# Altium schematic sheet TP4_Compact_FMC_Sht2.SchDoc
size B; SheetNumber: 2; SheetTotal: 2
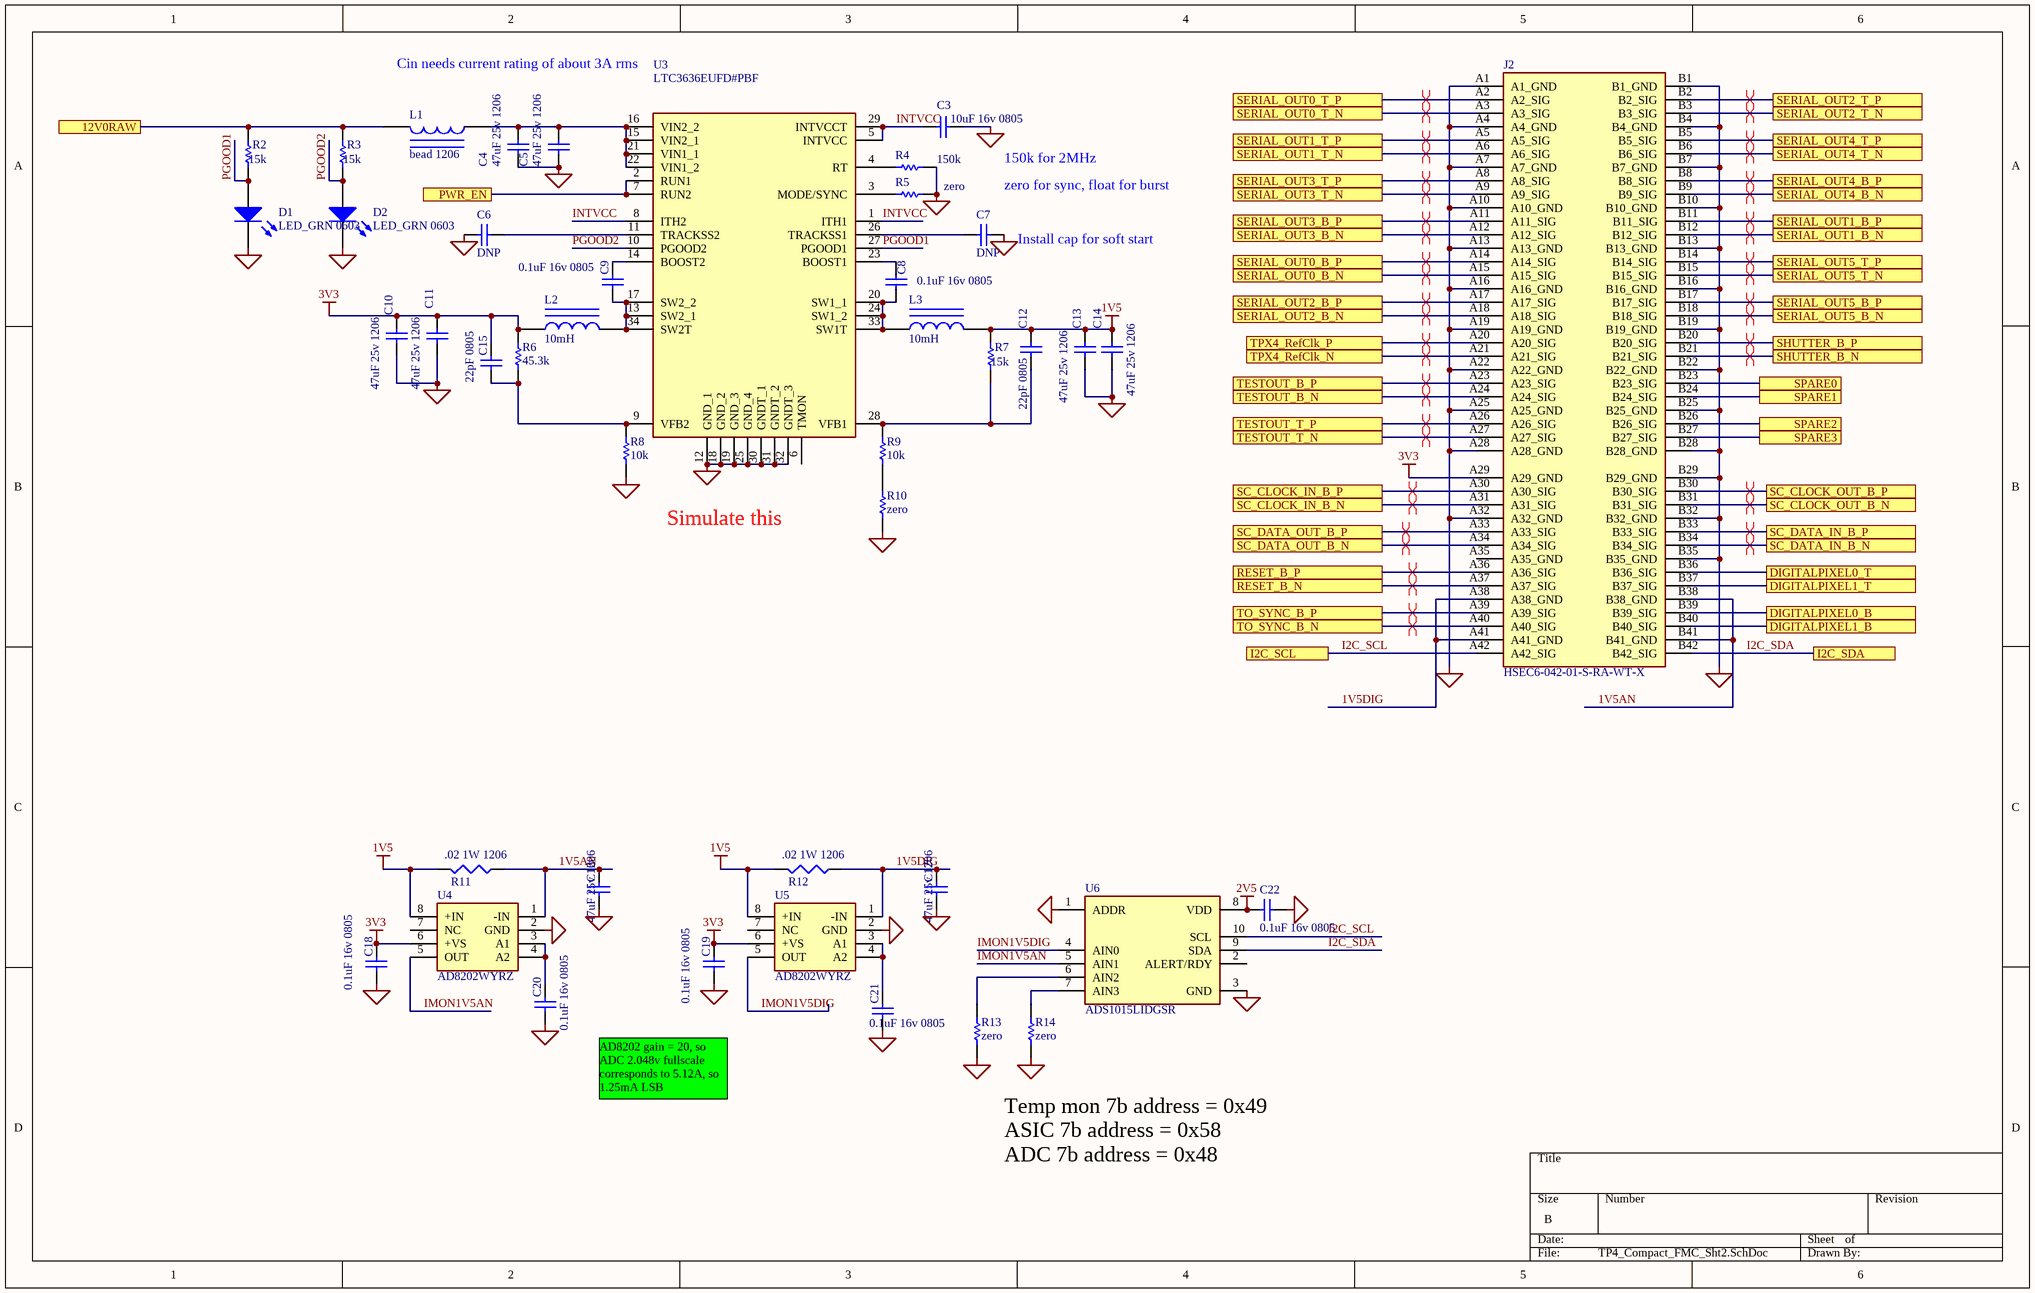
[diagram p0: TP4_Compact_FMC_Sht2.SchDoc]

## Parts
C3  value 10uF 16v 0805  [CAP0805]  (hidden comment: Cap)
C4  value 47uF 25v 1206  [1206]  (hidden comment: Cap)
C5  value 47uF 25v 1206  [1206]  (hidden comment: Cap)
C6  value DNP  [CAP0805]  (hidden comment: Cap)
C7  value DNP  [CAP0805]  (hidden comment: Cap)
C8  value 0.1uF 16v 0805  [CAP0805]  (hidden comment: Cap)
C9  value 0.1uF 16v 0805  [CAP0805]  (hidden comment: Cap)
C10  value 47uF 25v 1206  [1206]  (hidden comment: Cap)
C11  value 47uF 25v 1206  [1206]  (hidden comment: Cap)
C12  value 22pF 0805  [CAP0805]  (hidden comment: Cap)
C13  value 47uF 25v 1206  [1206]  (hidden comment: Cap)
C14  value 47uF 25v 1206  [1206]  (hidden comment: Cap)
C15  value 22pF 0805  [CAP0805]  (hidden comment: Cap)
C16  value 47uF 25v 1206  [1206]  (hidden comment: Cap)
C17  value 47uF 25v 1206  [1206]  (hidden comment: Cap)
C18  value 0.1uF 16v 0805  [CAP0805]  (hidden comment: Cap)
C19  value 0.1uF 16v 0805  [CAP0805]  (hidden comment: Cap)
C20  value 0.1uF 16v 0805  [CAP0805]  (hidden comment: Cap)
C21  value 0.1uF 16v 0805  [CAP0805]  (hidden comment: Cap)
C22  value 0.1uF 16v 0805  [CAP0805]  (hidden comment: Cap)
D1  LED_GRN 0603  [LED0603]
D2  LED_GRN 0603  [LED0603]
J2  HSEC6-042-01-S-RA-WT-X  [SAMTEC_HSEC6-042-01-S-RA-WT-X]
L1  value bead 1206  [1206]  (hidden comment: Inductor Iron)
L2  value 10mH  [Inductor_5.6mm]  (hidden comment: Inductor Iron)
L3  value 10mH  [Inductor_5.6mm]  (hidden comment: Inductor Iron)
R2  value 15k  [CAP0805]  (hidden comment: Res1)
R3  value 15k  [CAP0805]  (hidden comment: Res1)
R4  value 150k  [CAP0805]  (hidden comment: Res1)
R5  value zero  [CAP0805]  (hidden comment: Res1)
R6  value 45.3k  [CAP0805]  (hidden comment: Res1)
R7  value 15k  [CAP0805]  (hidden comment: Res1)
R8  value 10k  [CAP0805]  (hidden comment: Res1)
R9  value 10k  [CAP0805]  (hidden comment: Res1)
R10  value zero  [CAP0805]  (hidden comment: Res1)
R11  value .02 1W 1206  [CAP0805]  (hidden comment: Res)
R12  value .02 1W 1206  [CAP0805]  (hidden comment: Res)
R13  value zero  [CAP0805]  (hidden comment: Res1)
R14  value zero  [CAP0805]  (hidden comment: Res1)
U3  LTC3636EUFD#PBF  [LTC3636EUFDPBF]
U4  AD8202WYRZ  [SOIC127P600X175-8N]
U5  AD8202WYRZ  [SOIC127P600X175-8N]
U6  ADS1015LIDGSR  [SOP50P490X110-10N]

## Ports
12V0RAW (see TP4_Compact_FMC_Sht1[3D]), DIGITALPIXEL0_B (see TP4_Compact_FMC_Sht1[5B]), DIGITALPIXEL0_T (see TP4_Compact_FMC_Sht1[5B]), DIGITALPIXEL1_B (see TP4_Compact_FMC_Sht1[5B]), DIGITALPIXEL1_T (see TP4_Compact_FMC_Sht1[5B]), I2C_SCL (see TP4_Compact_FMC_Sht1[4B]), I2C_SDA (see TP4_Compact_FMC_Sht1[4B]), PWR_EN, RESET_B_N (see TP4_Compact_FMC_Sht1[5A]), RESET_B_P (see TP4_Compact_FMC_Sht1[5A]), SC_CLOCK_IN_B_N (see TP4_Compact_FMC_Sht1[4B]), SC_CLOCK_IN_B_P (see TP4_Compact_FMC_Sht1[4B]), SC_CLOCK_OUT_B_N (see TP4_Compact_FMC_Sht1[5A]), SC_CLOCK_OUT_B_P (see TP4_Compact_FMC_Sht1[5A]), SC_DATA_IN_B_N (see TP4_Compact_FMC_Sht1[5B]), SC_DATA_IN_B_P (see TP4_Compact_FMC_Sht1[5B]), SC_DATA_OUT_B_N (see TP4_Compact_FMC_Sht1[5A]), SC_DATA_OUT_B_P (see TP4_Compact_FMC_Sht1[5A]), SERIAL_OUT0_B_N (see TP4_Compact_FMC_Sht1[3A]), SERIAL_OUT0_B_P (see TP4_Compact_FMC_Sht1[3A]), SERIAL_OUT0_T_N (see TP4_Compact_FMC_Sht1[4A]), SERIAL_OUT0_T_P (see TP4_Compact_FMC_Sht1[4A]), SERIAL_OUT1_B_N (see TP4_Compact_FMC_Sht1[3A]), SERIAL_OUT1_B_P (see TP4_Compact_FMC_Sht1[3A]), SERIAL_OUT1_T_N (see TP4_Compact_FMC_Sht1[2A]), SERIAL_OUT1_T_P (see TP4_Compact_FMC_Sht1[2A]), SERIAL_OUT2_B_N (see TP4_Compact_FMC_Sht1[3A]), SERIAL_OUT2_B_P (see TP4_Compact_FMC_Sht1[3A]), SERIAL_OUT2_T_N (see TP4_Compact_FMC_Sht1[2A]), SERIAL_OUT2_T_P (see TP4_Compact_FMC_Sht1[2A]), SERIAL_OUT3_B_N (see TP4_Compact_FMC_Sht1[3A]), SERIAL_OUT3_B_P (see TP4_Compact_FMC_Sht1[3A]), SERIAL_OUT3_T_N (see TP4_Compact_FMC_Sht1[2A]), SERIAL_OUT3_T_P (see TP4_Compact_FMC_Sht1[2A]), SERIAL_OUT4_B_N (see TP4_Compact_FMC_Sht1[1A]), SERIAL_OUT4_B_P (see TP4_Compact_FMC_Sht1[1A]), SERIAL_OUT4_T_N (see TP4_Compact_FMC_Sht1[2A]), SERIAL_OUT4_T_P (see TP4_Compact_FMC_Sht1[2A]), SERIAL_OUT5_B_N (see TP4_Compact_FMC_Sht1[1A]), SERIAL_OUT5_B_P (see TP4_Compact_FMC_Sht1[1A]), SERIAL_OUT5_T_N (see TP4_Compact_FMC_Sht1[2A]), SERIAL_OUT5_T_P (see TP4_Compact_FMC_Sht1[2A]), SHUTTER_B_N (see TP4_Compact_FMC_Sht1[4B]), SHUTTER_B_P (see TP4_Compact_FMC_Sht1[4B]), SPARE0 (see TP4_Compact_FMC_Sht1[1C]), SPARE1 (see TP4_Compact_FMC_Sht1[1C]), SPARE2 (see TP4_Compact_FMC_Sht1[1C]), SPARE3 (see TP4_Compact_FMC_Sht1[1C]), TESTOUT_B_N (see TP4_Compact_FMC_Sht1[4A]), TESTOUT_B_P (see TP4_Compact_FMC_Sht1[4A]), TESTOUT_T_N (see TP4_Compact_FMC_Sht1[4A]), TESTOUT_T_P (see TP4_Compact_FMC_Sht1[4A]), TO_SYNC_B_N (see TP4_Compact_FMC_Sht1[5A]), TO_SYNC_B_P (see TP4_Compact_FMC_Sht1[5A]), TPX4_RefClk_N (see TP4_Compact_FMC_Sht1[4A]), TPX4_RefClk_P (see TP4_Compact_FMC_Sht1[4A])

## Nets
1V5: C12.2 C13.2 C14.2 L3.2 R7.2 R11.2 R12.2 U4.8(+IN) U5.8(+IN)
2V5: C22.2 U6.8(VDD)
3V3: C10.2 C11.2 C15.2 C18.2 C19.2 J2.A29(A29_GND) L2.1 R6.2 U4.6(+VS) U5.6(+VS)
GND: C3.1 C4.1 C5.1 C6.2 C7.1 C10.1 C11.1 C13.1 C14.1 C16.1 C17.1 C18.1 C19.1 C20.1 C21.1 C22.1 D1.2(K) D2.2(K) J2.A1(A1_GND) J2.A4(A4_GND) J2.A7(A7_GND) J2.A10(A10_GND) J2.A13(A13_GND) J2.A16(A16_GND) J2.A19(A19_GND) J2.A22(A22_GND) J2.A25(A25_GND) J2.A28(A28_GND) J2.A32(A32_GND) J2.B1(B1_GND) J2.B4(B4_GND) J2.B7(B7_GND) J2.B10(B10_GND) J2.B13(B13_GND) J2.B16(B16_GND) J2.B19(B19_GND) J2.B22(B22_GND) J2.B25(B25_GND) J2.B28(B28_GND) J2.B29(B29_GND) J2.B32(B32_GND) J2.B35(B35_GND) R4.1 R5.1 R8.1 R10.1 R13.1 R14.1 U3.12(GND_1) U3.18(GND_2) U3.19(GND_3) U3.25(GND_4) U3.30(GNDT_1) U3.31(GNDT_2) U3.32(GNDT_3) U4.2(GND) U5.2(GND) U6.1(ADDR) U6.3(GND)
1V5AN: C16.2 J2.B38(B38_GND) J2.B41(B41_GND) R11.1 U4.1(-IN)
1V5DIG: C17.2 J2.A38(A38_GND) J2.A41(A41_GND) R12.1 U5.1(-IN)
12V0RAW: L1.2 R2.2 R3.2 ; port 12V0RAW
DIGITALPIXEL0_B: J2.B39(B39_SIG) ; port DIGITALPIXEL0_B
DIGITALPIXEL0_T: J2.B36(B36_SIG) ; port DIGITALPIXEL0_T
DIGITALPIXEL1_B: J2.B40(B40_SIG) ; port DIGITALPIXEL1_B
DIGITALPIXEL1_T: J2.B37(B37_SIG) ; port DIGITALPIXEL1_T
I2C_SCL: J2.A42(A42_SIG) U6.10(SCL) ; port I2C_SCL
I2C_SDA: J2.B42(B42_SIG) U6.9(SDA) ; port I2C_SDA
IMON1V5AN: U4.5(OUT) U6.5(AIN1)
IMON1V5DIG: U5.5(OUT) U6.4(AIN0)
INTVCC: C3.2 U3.1(ITH1) U3.5(INTVCC) U3.8(ITH2) U3.29(INTVCCT)
PGOOD1: D1.1(A) R2.1 U3.27(PGOOD1)
PGOOD2: D2.1(A) R3.1 U3.10(PGOOD2)
PWR_EN: U3.2(RUN1) U3.7(RUN2) ; port PWR_EN
RESET_B_N: J2.A37(A37_SIG) ; port RESET_B_N
RESET_B_P: J2.A36(A36_SIG) ; port RESET_B_P
SC_CLOCK_IN_B_N: J2.A31(A31_SIG) ; port SC_CLOCK_IN_B_N
SC_CLOCK_IN_B_P: J2.A30(A30_SIG) ; port SC_CLOCK_IN_B_P
SC_CLOCK_OUT_B_N: J2.B31(B31_SIG) ; port SC_CLOCK_OUT_B_N
SC_CLOCK_OUT_B_P: J2.B30(B30_SIG) ; port SC_CLOCK_OUT_B_P
SC_DATA_IN_B_N: J2.B34(B34_SIG) ; port SC_DATA_IN_B_N
SC_DATA_IN_B_P: J2.B33(B33_SIG) ; port SC_DATA_IN_B_P
SC_DATA_OUT_B_N: J2.A34(A34_SIG) ; port SC_DATA_OUT_B_N
SC_DATA_OUT_B_P: J2.A33(A33_SIG) ; port SC_DATA_OUT_B_P
SERIAL_OUT0_B_N: J2.A15(A15_SIG) ; port SERIAL_OUT0_B_N
SERIAL_OUT0_B_P: J2.A14(A14_SIG) ; port SERIAL_OUT0_B_P
SERIAL_OUT0_T_N: J2.A3(A3_SIG) ; port SERIAL_OUT0_T_N
SERIAL_OUT0_T_P: J2.A2(A2_SIG) ; port SERIAL_OUT0_T_P
SERIAL_OUT1_B_N: J2.B12(B12_SIG) ; port SERIAL_OUT1_B_N
SERIAL_OUT1_B_P: J2.B11(B11_SIG) ; port SERIAL_OUT1_B_P
SERIAL_OUT1_T_N: J2.A6(A6_SIG) ; port SERIAL_OUT1_T_N
SERIAL_OUT1_T_P: J2.A5(A5_SIG) ; port SERIAL_OUT1_T_P
SERIAL_OUT2_B_N: J2.A18(A18_SIG) ; port SERIAL_OUT2_B_N
SERIAL_OUT2_B_P: J2.A17(A17_SIG) ; port SERIAL_OUT2_B_P
SERIAL_OUT2_T_N: J2.B3(B3_SIG) ; port SERIAL_OUT2_T_N
SERIAL_OUT2_T_P: J2.B2(B2_SIG) ; port SERIAL_OUT2_T_P
SERIAL_OUT3_B_N: J2.A12(A12_SIG) ; port SERIAL_OUT3_B_N
SERIAL_OUT3_B_P: J2.A11(A11_SIG) ; port SERIAL_OUT3_B_P
SERIAL_OUT3_T_N: J2.A9(A9_SIG) ; port SERIAL_OUT3_T_N
SERIAL_OUT3_T_P: J2.A8(A8_SIG) ; port SERIAL_OUT3_T_P
SERIAL_OUT4_B_N: J2.B9(B9_SIG) ; port SERIAL_OUT4_B_N
SERIAL_OUT4_B_P: J2.B8(B8_SIG) ; port SERIAL_OUT4_B_P
SERIAL_OUT4_T_N: J2.B6(B6_SIG) ; port SERIAL_OUT4_T_N
SERIAL_OUT4_T_P: J2.B5(B5_SIG) ; port SERIAL_OUT4_T_P
SERIAL_OUT5_B_N: J2.B18(B18_SIG) ; port SERIAL_OUT5_B_N
SERIAL_OUT5_B_P: J2.B17(B17_SIG) ; port SERIAL_OUT5_B_P
SERIAL_OUT5_T_N: J2.B15(B15_SIG) ; port SERIAL_OUT5_T_N
SERIAL_OUT5_T_P: J2.B14(B14_SIG) ; port SERIAL_OUT5_T_P
SHUTTER_B_N: J2.B21(B21_SIG) ; port SHUTTER_B_N
SHUTTER_B_P: J2.B20(B20_SIG) ; port SHUTTER_B_P
SPARE0: J2.B23(B23_SIG) ; port SPARE0
SPARE1: J2.B24(B24_SIG) ; port SPARE1
SPARE2: J2.B26(B26_SIG) ; port SPARE2
SPARE3: J2.B27(B27_SIG) ; port SPARE3
TESTOUT_B_N: J2.A24(A24_SIG) ; port TESTOUT_B_N
TESTOUT_B_P: J2.A23(A23_SIG) ; port TESTOUT_B_P
TESTOUT_T_N: J2.A27(A27_SIG) ; port TESTOUT_T_N
TESTOUT_T_P: J2.A26(A26_SIG) ; port TESTOUT_T_P
TO_SYNC_B_N: J2.A40(A40_SIG) ; port TO_SYNC_B_N
TO_SYNC_B_P: J2.A39(A39_SIG) ; port TO_SYNC_B_P
TPX4_RefClk_N: J2.A21(A21_SIG) ; port TPX4_RefClk_N
TPX4_RefClk_P: J2.A20(A20_SIG) ; port TPX4_RefClk_P
NetC4_2: C4.2 C5.2 L1.1 U3.15(VIN2_1) U3.16(VIN2_2) U3.21(VIN1_1) U3.22(VIN1_2)
NetC6_1: C6.1 U3.11(TRACKSS2)
NetC7_2: C7.2 U3.26(TRACKSS1)
NetC8_1: C8.1 L3.1 U3.20(SW1_1) U3.24(SW1_2) U3.33(SW1T)
NetC8_2: C8.2 U3.23(BOOST1)
NetC9_1: C9.1 L2.2 U3.13(SW2_1) U3.17(SW2_2) U3.34(SW2T)
NetC9_2: C9.2 U3.14(BOOST2)
NetC12_1: C12.1 R7.1 R9.2 U3.28(VFB1)
NetC15_1: C15.1 R6.1 R8.2 U3.9(VFB2)
NetC20_2: C20.2 U4.3(A1) U4.4(A2)
NetC21_2: C21.2 U5.3(A1) U5.4(A2)
NetR4_2: R4.2 U3.4(RT)
NetR5_2: R5.2 U3.3(MODE/SYNC)
NetR9_1: R9.1 R10.2
NetR13_2: R13.2 U6.6(AIN2)
NetR14_2: R14.2 U6.7(AIN3)

Not connected (* = marked no-connect by the designer): J2 A35(A35_GND); U3 6(TMON); U4 7(NC); U5 7(NC); U6 2(ALERT/RDY)

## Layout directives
differential pair: RESET_B_N, RESET_B_P, SC_CLOCK_IN_B_N, SC_CLOCK_IN_B_P, SC_CLOCK_OUT_B_N, SC_CLOCK_OUT_B_P, SC_DATA_IN_B_N, SC_DATA_IN_B_P, SC_DATA_OUT_B_N, SC_DATA_OUT_B_P, SERIAL_OUT0_B_N, SERIAL_OUT0_B_P, SERIAL_OUT0_T_N, SERIAL_OUT0_T_P, SERIAL_OUT1_B_N, SERIAL_OUT1_B_P, SERIAL_OUT1_T_N, SERIAL_OUT1_T_P, SERIAL_OUT2_B_N, SERIAL_OUT2_B_P, SERIAL_OUT2_T_N, SERIAL_OUT2_T_P, SERIAL_OUT3_B_N, SERIAL_OUT3_B_P, SERIAL_OUT3_T_N, SERIAL_OUT3_T_P, SERIAL_OUT4_B_N, SERIAL_OUT4_B_P, SERIAL_OUT4_T_N, SERIAL_OUT4_T_P, SERIAL_OUT5_B_N, SERIAL_OUT5_B_P, SERIAL_OUT5_T_N, SERIAL_OUT5_T_P, SHUTTER_B_N, SHUTTER_B_P, TESTOUT_B_N, TESTOUT_B_P, TESTOUT_T_N, TESTOUT_T_P, TO_SYNC_B_N, TO_SYNC_B_P, TPX4_RefClk_N, TPX4_RefClk_P

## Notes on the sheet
- Cin needs current rating of about 3A rms
- 150k for 2MHz
- (near C7) zero for sync, float for burst
- (near C7) Install cap for soft start
- Simulate this
- AD8202 gain = 20, so ADC 2.048v fullscale corresponds to 5.12A, so 1.25mA LSB
- Temp mon 7b address = 0x49
  ASIC 7b address = 0x58
  ADC 7b address = 0x48

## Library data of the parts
C3 = Cap: Capacitor; OrderNo: 1276-2872-1-ND
C4 C5 C10 C11 C13 C14 C16 C17 = Cap: Capacitor; OrderNo: 445-8047-1-ND
C6 C7 = Cap: Capacitor
C8 C9 C18-C22 = Cap: Capacitor; OrderNo: 399-C0805C104K4RACTUCT-ND; CostEach: 0
C12 C15 = Cap: Capacitor; OrderNo: 399-C0805C220J5GACTUCT-ND
D1 D2 = LED2: Red LED, SM; EM_PN: L62301CT-ND; OrderNo: L62305CT-ND
J2 = HSEC6-042-01-S-RA-WT-X: 84 Position Female Connector PCI Expressâ„¢ Gold 0.024 (0.60mm) Black; MF: Samtec Inc.; MP: HSEC6-042-01-S-RA-WT-TR
L1 = Inductor Iron: Magnetic-Core Inductor
L2 L3 = Inductor Iron: Magnetic-Core Inductor; OrderNo: DK 732-6173-1-ND
R2-R10 R13 R14 = Res1: Resistor
R11 R12 = Res: Resistor, SM; OrderNo: RHM.003ALCT-ND; CostEach: 0
U3 = LTC3636EUFD#PBF: Integrated Circuit; Manufacturer_Name: Analog Devices
U4 U5 = AD8202WYRZ: Integrated Circuit; Manufacturer_Name: Analog Devices; OrderNo: AD8202YRZ-R7CT-ND
U6 = ADS1015LIDGSR: Integrated Circuit; Manufacturer_Name: Texas Instruments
